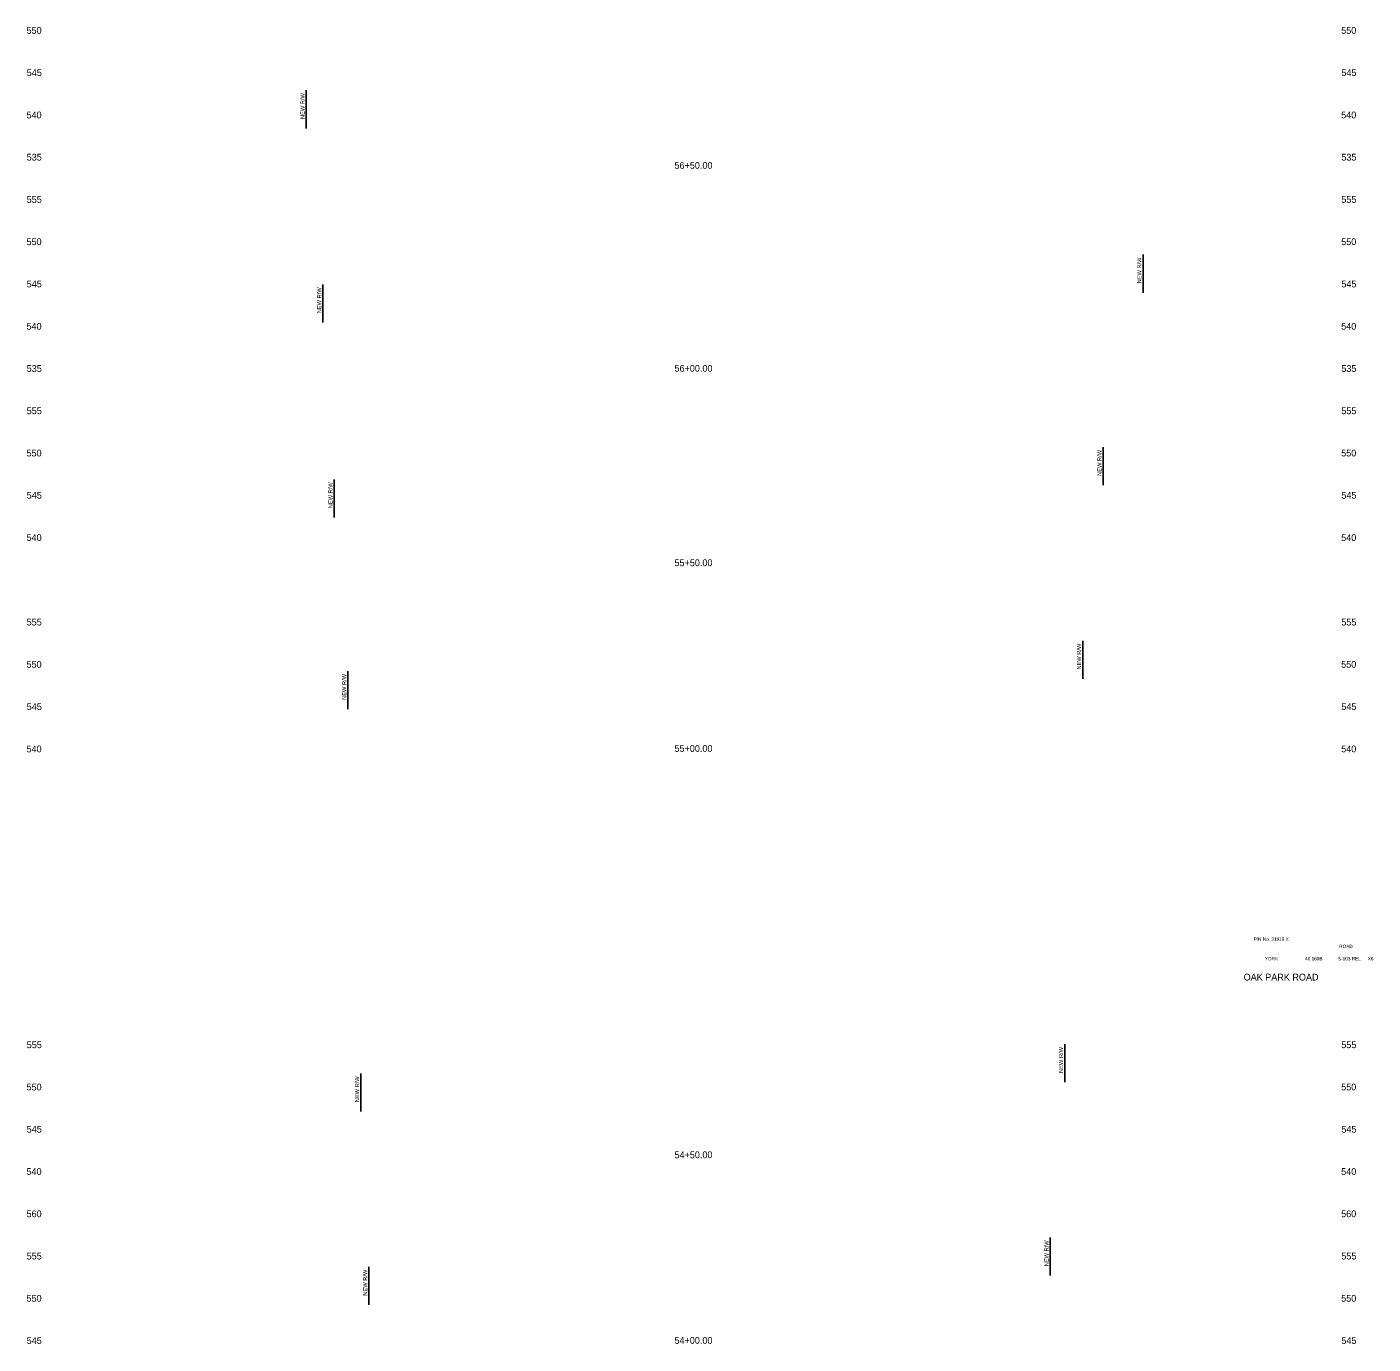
# Model space of a CAD drawing. Extents: x 1001 to 1161, y 1005 to 3518.
# Drawn here: x 1001.2 to 1160.4, y 1630.1 to 1785.9 of the extents above; entities that cross this region are included whole.
import ezdxf

# ---------------------------------------------------------------- set-up
doc = ezdxf.new("R2010")
doc.units = 0
for name, color, linetype in [('RD_SHT_TX', 7, 'Continuous'), ('RD_XS_NewRW', 7, 'Continuous'), ('RD_XS_TX_Elev_EX', 7, 'Continuous'), ('RD_XS_TX_Station', 7, 'Continuous')]:
    doc.layers.add(name, color=color, linetype=linetype)

msp = doc.modelspace()

# ---------------------------------------------------------------- linework, layer by layer
at = {"layer": 'RD_XS_NewRW'}
for p, q in [((1034.23, 1778.41), (1034.23, 1773.91)), ((1133.2, 1758.97), (1133.2, 1754.47)), ((1036.2, 1755.43), (1036.2, 1750.93)), ((1128.5, 1736.2), (1128.5, 1731.7)), ((1037.54, 1732.36), (1037.54, 1727.86)), ((1126.08, 1713.28), (1126.08, 1708.78)), ((1039.16, 1709.7), (1039.16, 1705.2)), ((1123.95, 1665.56), (1123.95, 1661.06)), ((1040.68, 1662.09), (1040.68, 1657.59)), ((1122.23, 1642.69), (1122.23, 1638.19)), ((1041.64, 1639.22), (1041.64, 1634.72))]:
    msp.add_line(p, q, dxfattribs=at)

# ---------------------------------------------------------------- texts
at = {"layer": 'RD_SHT_TX'}
for s, height, p in [('PIN No. 31919 X', 0.4, (1146.29, 1677.8)), ('ROAD', 0.4, (1156.41, 1676.93)), ('YORK', 0.4, (1147.61, 1675.48)), ('46.169B', 0.4, (1152.37, 1675.48)), ('S-103 REL', 0.4, (1156.26, 1675.48)), ('X6', 0.4, (1159.78, 1675.48)), ('OAK PARK ROAD', 0.8, (1145.1, 1673.1))]:
    msp.add_text(s, height=height, dxfattribs=at).set_placement(p)
at = {"layer": 'RD_XS_NewRW'}
for p in [(1034.03, 1775.01), (1133, 1755.57), (1036, 1752.04), (1128.3, 1732.8), (1037.34, 1728.97), (1125.88, 1709.88), (1038.96, 1706.3), (1123.74, 1662.16), (1040.48, 1658.69), (1122.03, 1639.29), (1041.44, 1635.82)]:
    msp.add_text('NEW R/W ', height=0.488, rotation=90, dxfattribs=at).set_placement(p)
at = {"layer": 'RD_XS_TX_Elev_EX'}
for s, p in [('550', (1001.14, 1785.1)), ('550', (1156.64, 1785.1)), ('545', (1001.16, 1780.1)), ('545', (1156.66, 1780.1)), ('540', (1001.14, 1775.1)), ('540', (1156.64, 1775.1)), ('535', (1001.16, 1770.1)), ('535', (1156.66, 1770.1)), ('555', (1001.16, 1765.1)), ('555', (1156.66, 1765.1)), ('550', (1001.14, 1760.1)), ('550', (1156.64, 1760.1)), ('545', (1001.16, 1755.1)), ('545', (1156.66, 1755.1)), ('540', (1001.14, 1750.1)), ('540', (1156.64, 1750.1)), ('535', (1001.16, 1745.1)), ('535', (1156.66, 1745.1)), ('555', (1001.16, 1740.1)), ('555', (1156.66, 1740.1)), ('550', (1001.14, 1735.1)), ('550', (1156.64, 1735.1)), ('545', (1001.16, 1730.1)), ('545', (1156.66, 1730.1)), ('540', (1001.14, 1725.1)), ('540', (1156.64, 1725.1)), ('555', (1001.16, 1715.1)), ('555', (1156.66, 1715.1)), ('550', (1001.14, 1710.1)), ('550', (1156.64, 1710.1)), ('545', (1001.16, 1705.1)), ('545', (1156.66, 1705.1)), ('540', (1001.14, 1700.1)), ('540', (1156.64, 1700.1)), ('555', (1001.16, 1665.1)), ('555', (1156.66, 1665.1)), ('550', (1001.14, 1660.1)), ('550', (1156.64, 1660.1)), ('545', (1001.16, 1655.1)), ('545', (1156.66, 1655.1)), ('540', (1001.14, 1650.1)), ('540', (1156.64, 1650.1)), ('560', (1001.14, 1645.1)), ('560', (1156.64, 1645.1)), ('555', (1001.16, 1640.1)), ('555', (1156.66, 1640.1)), ('550', (1001.14, 1635.1)), ('550', (1156.64, 1635.1)), ('545', (1001.16, 1630.1)), ('545', (1156.66, 1630.1))]:
    msp.add_text(s, height=0.8, dxfattribs=at).set_placement(p)
at = {"layer": 'RD_XS_TX_Station'}
for s, p in [('56+50.00', (1077.78, 1769.13)), ('56+00.00', (1077.78, 1745.12)), ('55+50.00', (1077.78, 1722.12)), ('55+00.00', (1077.78, 1700.15)), ('54+50.00', (1077.78, 1652.08)), ('54+00.00', (1077.78, 1630.12))]:
    msp.add_text(s, height=0.8, dxfattribs=at).set_placement(p)

doc.saveas('drawing.dxf')
